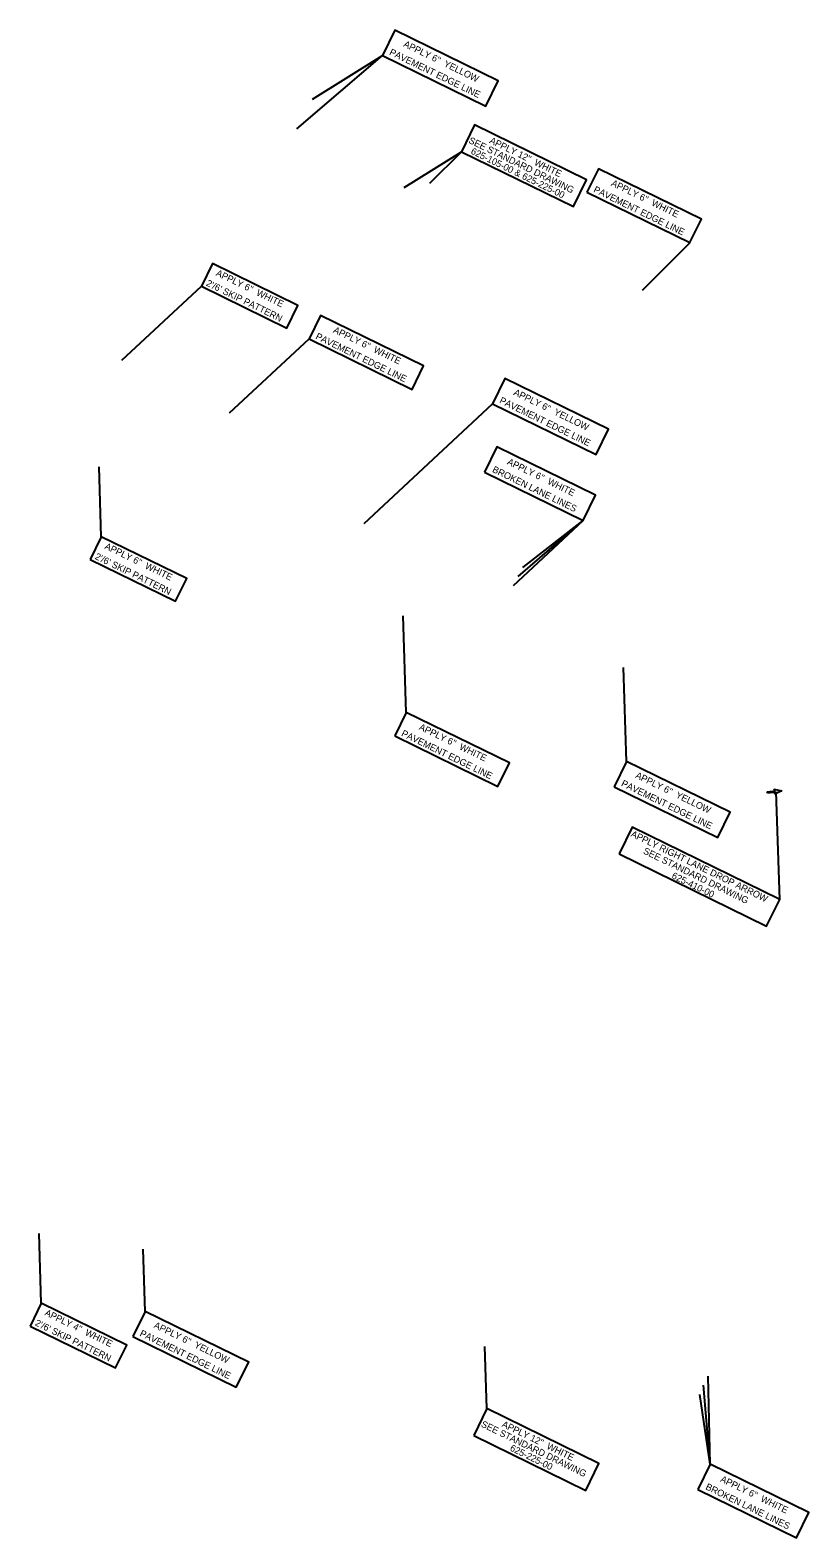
# Model space of a CAD drawing. Extents: x 1966013 to 1974896, y 789499 to 804826.
# Drawn here: x 1972940 to 1973867, y 793220 to 795016 of the extents above; entities that cross this region are included whole.
import ezdxf

# ---------------------------------------------------------------- set-up
doc = ezdxf.new("R2010")
doc.units = 0
doc.layers.add('RD_EX_H2O_BlueLn', color=7, linetype='Continuous')

msp = doc.modelspace()

# ---------------------------------------------------------------- linework, layer by layer
at = {"layer": 'RD_EX_H2O_BlueLn'}
for p, q in [((1973257.4, 794898.3), (1973359.1, 794985.8)), ((1973275.9, 794933.7), (1973359.1, 794985.8)), ((1973384.9, 794828.3), (1973453.2, 794871.1)), ((1973415.7, 794833.6), (1973453.2, 794871.1)), ((1973669, 794706.3), (1973725.5, 794762.8)), ((1973049.1, 794622.7), (1973143.6, 794710.8)), ((1973177.3, 794559.9), (1973271.8, 794648.1)), ((1973337.3, 794428.1), (1973490.2, 794570.8)), ((1973024.4, 794412.4), (1973021.8, 794495.8)), ((1973515.3, 794354.3), (1973598.4, 794431.8)), ((1973520.7, 794365.1), (1973598.4, 794431.8)), ((1973526.2, 794375.7), (1973598.4, 794431.8)), ((1973387.6, 794203.2), (1973383.9, 794318.4)), ((1973650, 794144.8), (1973646.4, 794256.7)), ((1973817.5, 794108.8), (1973827.2, 794109.9)), ((1973817.7, 794107), (1973817.5, 794108.8)), ((1973827.4, 794108.1), (1973817.7, 794107)), ((1973825.2, 794111.7), (1973834.6, 794109.8)), ((1973827.2, 794109.9), (1973825.2, 794111.7)), ((1973834.6, 794109.8), (1973825.9, 794105.8)), ((1973825.9, 794105.8), (1973827.4, 794108.1)), ((1973832.2, 793980.6), (1973828.1, 794108.7)), ((1972953, 793499.5), (1972950.4, 793582.7)), ((1973076.6, 793489.9), (1973074.3, 793563.9)), ((1973483.6, 793374), (1973481.3, 793448)), ((1973749.4, 793307.7), (1973741.7, 793401.9)), ((1973749.4, 793307.7), (1973747.2, 793412.7)), ((1973749.4, 793307.7), (1973737.3, 793390.7))]:
    msp.add_line(p, q, dxfattribs=at)
for points in [[(1973359.1, 794985.8), (1973482.5, 794925.4), (1973497.2, 794955.5), (1973373.8, 795015.9)], [(1973453.2, 794871.1), (1973586.6, 794805.7), (1973602.2, 794837.6), (1973468.8, 794903)], [(1973602.6, 794822.9), (1973725.4, 794762.8), (1973739.1, 794790.8), (1973616.4, 794850.9)], [(1973143.6, 794710.8), (1973245.4, 794661), (1973258.6, 794688.1), (1973156.9, 794737.9)], [(1973271.8, 794648.1), (1973394.5, 794587.9), (1973408.2, 794615.9), (1973285.5, 794676)], [(1973490.2, 794570.8), (1973613.6, 794510.4), (1973628.3, 794540.5), (1973504.9, 794600.9)], [(1973480.9, 794489.4), (1973598.4, 794431.8), (1973613.1, 794461.9), (1973495.6, 794519.4)], [(1973011.2, 794385.4), (1973112.9, 794335.6), (1973126.2, 794362.6), (1973024.4, 794412.4)], [(1973373.9, 794175.2), (1973496.7, 794115.1), (1973510.4, 794143.1), (1973387.6, 794203.2)], [(1973635.3, 794114.7), (1973758.6, 794054.3), (1973773.3, 794084.4), (1973650, 794144.8)], [(1973641, 794034.7), (1973816.6, 793948.7), (1973832.2, 793980.6), (1973656.7, 794066.6)], [(1972939.8, 793472.4), (1973041.5, 793422.6), (1973054.8, 793449.7), (1972953, 793499.5)], [(1973061.9, 793459.8), (1973185.2, 793399.4), (1973200, 793429.5), (1973076.6, 793489.9)], [(1973468, 793342), (1973601.4, 793276.7), (1973617, 793308.6), (1973483.6, 793374)], [(1973734.7, 793277.6), (1973852.2, 793220.1), (1973866.9, 793250.2), (1973749.4, 793307.7)]]:
    msp.add_lwpolyline(points, close=True, dxfattribs=at)

# ---------------------------------------------------------------- texts
for s, height, rotation, p in [("APPLY 6''  YELLOW", 8, 333.9112, (1973383.5, 794996.7)), ('PAVEMENT EDGE LINE', 8, 333.9112, (1973366.7, 794987.1)), ('SEE STANDARD DRAWING', 8, 333.9112, (1973461.1, 794881.9)), ('625-105-00 & 625-225-00', 8, 333.9112, (1973463.7, 794869.1)), ("APPLY 12''  WHITE", 8, 333.9112, (1973485.9, 794881.8)), ('PAVEMENT EDGE LINE', 8, 333.9112, (1973609.8, 794823.4)), ("APPLY 6''  WHITE", 8, 333.9112, (1973630.8, 794831)), ("APPLY 6''  WHITE", 7.999, 333.9114, (1973160.3, 794724)), ("2'/6' SKIP PATTERN", 7.999, 333.9114, (1973148.6, 794711.9)), ("APPLY 6''  WHITE", 8, 333.9112, (1973299.9, 794656.1)), ('PAVEMENT EDGE LINE', 8, 333.9112, (1973278.9, 794648.6)), ("APPLY 6''  YELLOW", 8, 333.9112, (1973514.6, 794581.8)), ('PAVEMENT EDGE LINE', 8, 333.9112, (1973497.8, 794572.2)), ('BROKEN LANE LINES', 8, 333.9112, (1973489.3, 794490)), ("APPLY 6''  WHITE", 8, 333.9112, (1973507, 794499.2)), ("2'/6' SKIP PATTERN", 7.999, 333.9114, (1973016.2, 794386.4)), ("APPLY 6''  WHITE", 7.999, 333.9114, (1973027.8, 794398.6)), ('PAVEMENT EDGE LINE', 8, 333.9112, (1973381, 794175.7)), ("APPLY 6''  WHITE", 8, 333.9112, (1973402, 794183.2)), ('PAVEMENT EDGE LINE', 8, 333.9112, (1973642.8, 794116.1)), ("APPLY 6''  YELLOW", 8, 333.9112, (1973659.7, 794125.7)), ('APPLY RIGHT LANE DROP ARROW', 8, 333.9112, (1973654.3, 794055.9)), ('SEE STANDARD DRAWING', 8, 333.9112, (1973668.9, 794035.6)), ('625-410-00 ', 7.999, 333.9112, (1973702.9, 794006.2)), ("APPLY 4''  WHITE", 7.999, 333.9114, (1972956.4, 793485.6)), ("2'/6' SKIP PATTERN", 7.999, 333.9114, (1972944.8, 793473.5)), ("APPLY 6''  YELLOW", 8, 333.9112, (1973086.3, 793470.7)), ('PAVEMENT EDGE LINE', 8, 333.9112, (1973069.5, 793461.1)), ('SEE STANDARD DRAWING', 8, 333.9112, (1973475.9, 793352.9)), ("APPLY 12''  WHITE", 8, 333.9112, (1973500.7, 793352.8)), ('625-225-00', 8, 333.9112, (1973510.3, 793324.5)), ("APPLY 6''  WHITE", 8, 333.9112, (1973760.8, 793287.5)), ('BROKEN LANE LINES', 8, 333.9112, (1973743.2, 793278.3))]:
    msp.add_text(s, height=height, rotation=rotation, dxfattribs=at).set_placement(p)

doc.saveas('drawing.dxf')
